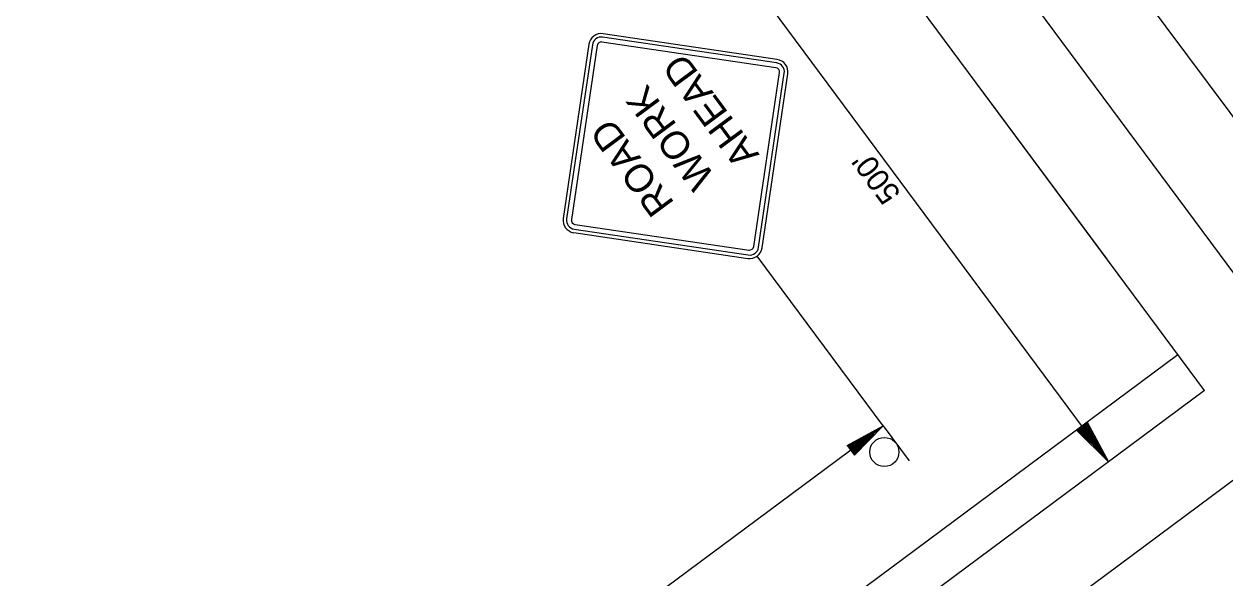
# Model space of a CAD drawing. Extents: x 998982 to 1000630, y 1875366 to 1876934.
# Drawn here: x 999829.6 to 1000152.3, y 1876255.9 to 1876404.6 of the extents above; entities that cross this region are included whole.
import ezdxf

# ---------------------------------------------------------------- set-up
doc = ezdxf.new("R2010")
doc.units = 0
for name, color, linetype in [('P_TC_Signs_Temporary', 7, 'Continuous'), ('R_Border Prem', 7, 'Continuous'), ('R_Draft', 7, 'Continuous'), ('STAMP', 7, 'Continuous')]:
    doc.layers.add(name, color=color, linetype=linetype)

msp = doc.modelspace()

# ---------------------------------------------------------------- linework, layer by layer
at = {"layer": 'P_TC_Signs_Temporary'}
for p, q in [((999981.38, 1876399.16), (999974.47, 1876352.42)), ((999982.31, 1876399.03), (999975.4, 1876352.28)), ((1000031.62, 1876392.88), (999984.88, 1876399.78)), ((1000031.82, 1876394.17), (999985.07, 1876401.08)), ((1000031.95, 1876395.1), (999985.21, 1876402.01)), ((999983.6, 1876398.83), (999976.7, 1876352.09)), ((1000025.67, 1876344.86), (1000032.57, 1876391.6)), ((1000026.96, 1876344.66), (1000033.87, 1876391.41)), ((1000027.89, 1876344.53), (1000034.8, 1876391.27)), ((999977.65, 1876350.81), (1000024.39, 1876343.91)), ((999977.32, 1876348.59), (1000024.06, 1876341.68)), ((999977.45, 1876349.52), (1000024.2, 1876342.61))]:
    msp.add_line(p, q, dxfattribs=at)
for centre, radius, start, end in [((999984.72, 1876398.67), 3.38, 81.5953, 171.5953), ((999984.72, 1876398.67), 2.44, 81.5953, 171.5953), ((999984.72, 1876398.67), 1.12, 81.5953, 171.5953), ((1000031.46, 1876391.76), 1.13, 351.5953, 81.5953), ((1000031.46, 1876391.76), 2.44, 351.5953, 81.5953), ((1000031.46, 1876391.76), 3.38, 351.5953, 81.5953), ((999977.81, 1876351.93), 3.38, 171.5953, 261.5953), ((999977.81, 1876351.93), 2.44, 171.5953, 261.5953), ((999977.81, 1876351.93), 1.13, 171.5953, 261.5953), ((1000024.55, 1876345.02), 3.38, 261.5953, 351.5953), ((1000024.55, 1876345.02), 2.44, 261.5953, 351.5953), ((1000024.55, 1876345.02), 1.12, 261.5953, 351.5953)]:
    msp.add_arc(centre, radius, start, end, dxfattribs=at)
at = {"layer": 'R_Draft'}
for p, q in [((1000356.62, 1876107.48), (1000045.75, 1876526.13)), ((1000025.68, 1876511.22), (1000336.54, 1876092.57)), ((1000146.77, 1876306.21), (1000005.61, 1876496.32)), ((1000120.96, 1876287.05), (1000001.73, 1876447.62)), ((1000120.6, 1876341.47), (1000086.78, 1876387.02)), ((1000060.39, 1876296.76), (1000026.56, 1876342.31)), ((1000139.63, 1876315.82), (999829.63, 1876085.64)), ((1000146.77, 1876306.21), (999836.77, 1876076.03)), ((1000181.11, 1876301.9), (999851.04, 1876056.81)), ((999879.74, 1876162.62), (1000060.39, 1876296.76)), ((1000050.77, 1876291.42), (1000060.39, 1876296.76)), ((1000052.76, 1876288.83), (1000060.39, 1876296.76)), ((1000115.26, 1876297.73), (1000112.38, 1876295.59)), ((1000112.62, 1876295.77), (1000119.77, 1876288.65)), ((1000112.87, 1876295.95), (1000118.54, 1876290.31)), ((1000113.11, 1876296.13), (1000117.35, 1876291.91)), ((1000113.35, 1876296.31), (1000116.14, 1876293.53)), ((1000113.6, 1876296.49), (1000114.95, 1876295.14)), ((1000114.05, 1876296.83), (1000114.95, 1876295.14)), ((1000114.29, 1876297), (1000116.14, 1876293.53)), ((1000114.54, 1876297.19), (1000117.35, 1876291.91)), ((1000114.78, 1876297.37), (1000118.54, 1876290.31)), ((1000115.02, 1876297.55), (1000119.77, 1876288.65)), ((1000115.26, 1876297.73), (1000120.96, 1876287.05)), ((1000050.93, 1876291.21), (1000058.95, 1876295.65)), ((1000051.1, 1876290.99), (1000057.47, 1876294.51)), ((1000051.27, 1876290.77), (1000056.03, 1876293.4)), ((1000052.25, 1876289.49), (1000056.03, 1876293.4)), ((1000052.42, 1876289.27), (1000057.47, 1876294.51)), ((1000052.59, 1876289.05), (1000058.95, 1876295.65)), ((1000112.38, 1876295.59), (1000120.96, 1876287.05)), ((1000050.77, 1876291.42), (1000052.76, 1876288.83)), ((1000051.44, 1876290.55), (1000054.56, 1876292.28)), ((1000051.6, 1876290.33), (1000053.12, 1876291.17)), ((1000051.92, 1876289.93), (1000053.12, 1876291.17)), ((1000052.08, 1876289.71), (1000054.56, 1876292.28))]:
    msp.add_line(p, q, dxfattribs=at)
at = {"layer": 'STAMP'}
msp.add_line((1000060.39, 1876296.76), (1000067.4, 1876287.32), dxfattribs=at)
msp.add_circle((1000060.75, 1876289.7), 3.92, dxfattribs=at)

# ---------------------------------------------------------------- texts
at = {"layer": 'P_TC_Signs_Temporary'}
for s, p in [('AHEAD', (1000027.31, 1876369.55)), ('WORK', (1000015.49, 1876363.62)), (' ROAD ', (1000006.19, 1876354.29))]:
    msp.add_text(s, height=7.5, rotation=126.5953, dxfattribs=at).set_placement(p)
at = {"layer": 'R_Border Prem'}
msp.add_text("500'", height=6, rotation=126.5953, dxfattribs=at).set_placement((1000065.4, 1876359.1))

doc.saveas('drawing.dxf')
